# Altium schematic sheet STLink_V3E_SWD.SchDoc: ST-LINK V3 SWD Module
size A3; Date: Not used; ApprovedBy: Not used; CheckedBy: Not used; Author: Not used; CompanyName: STMicroelectronics; DrawnBy: Not used; Engineer: Not used; Organization: Not used; Address1: Not used; Address2: Not used; Address3: Not used; Address4: Not used; DocumentNumber: Not used; Revision: Not used; SheetNumber: 23; SheetTotal: 23
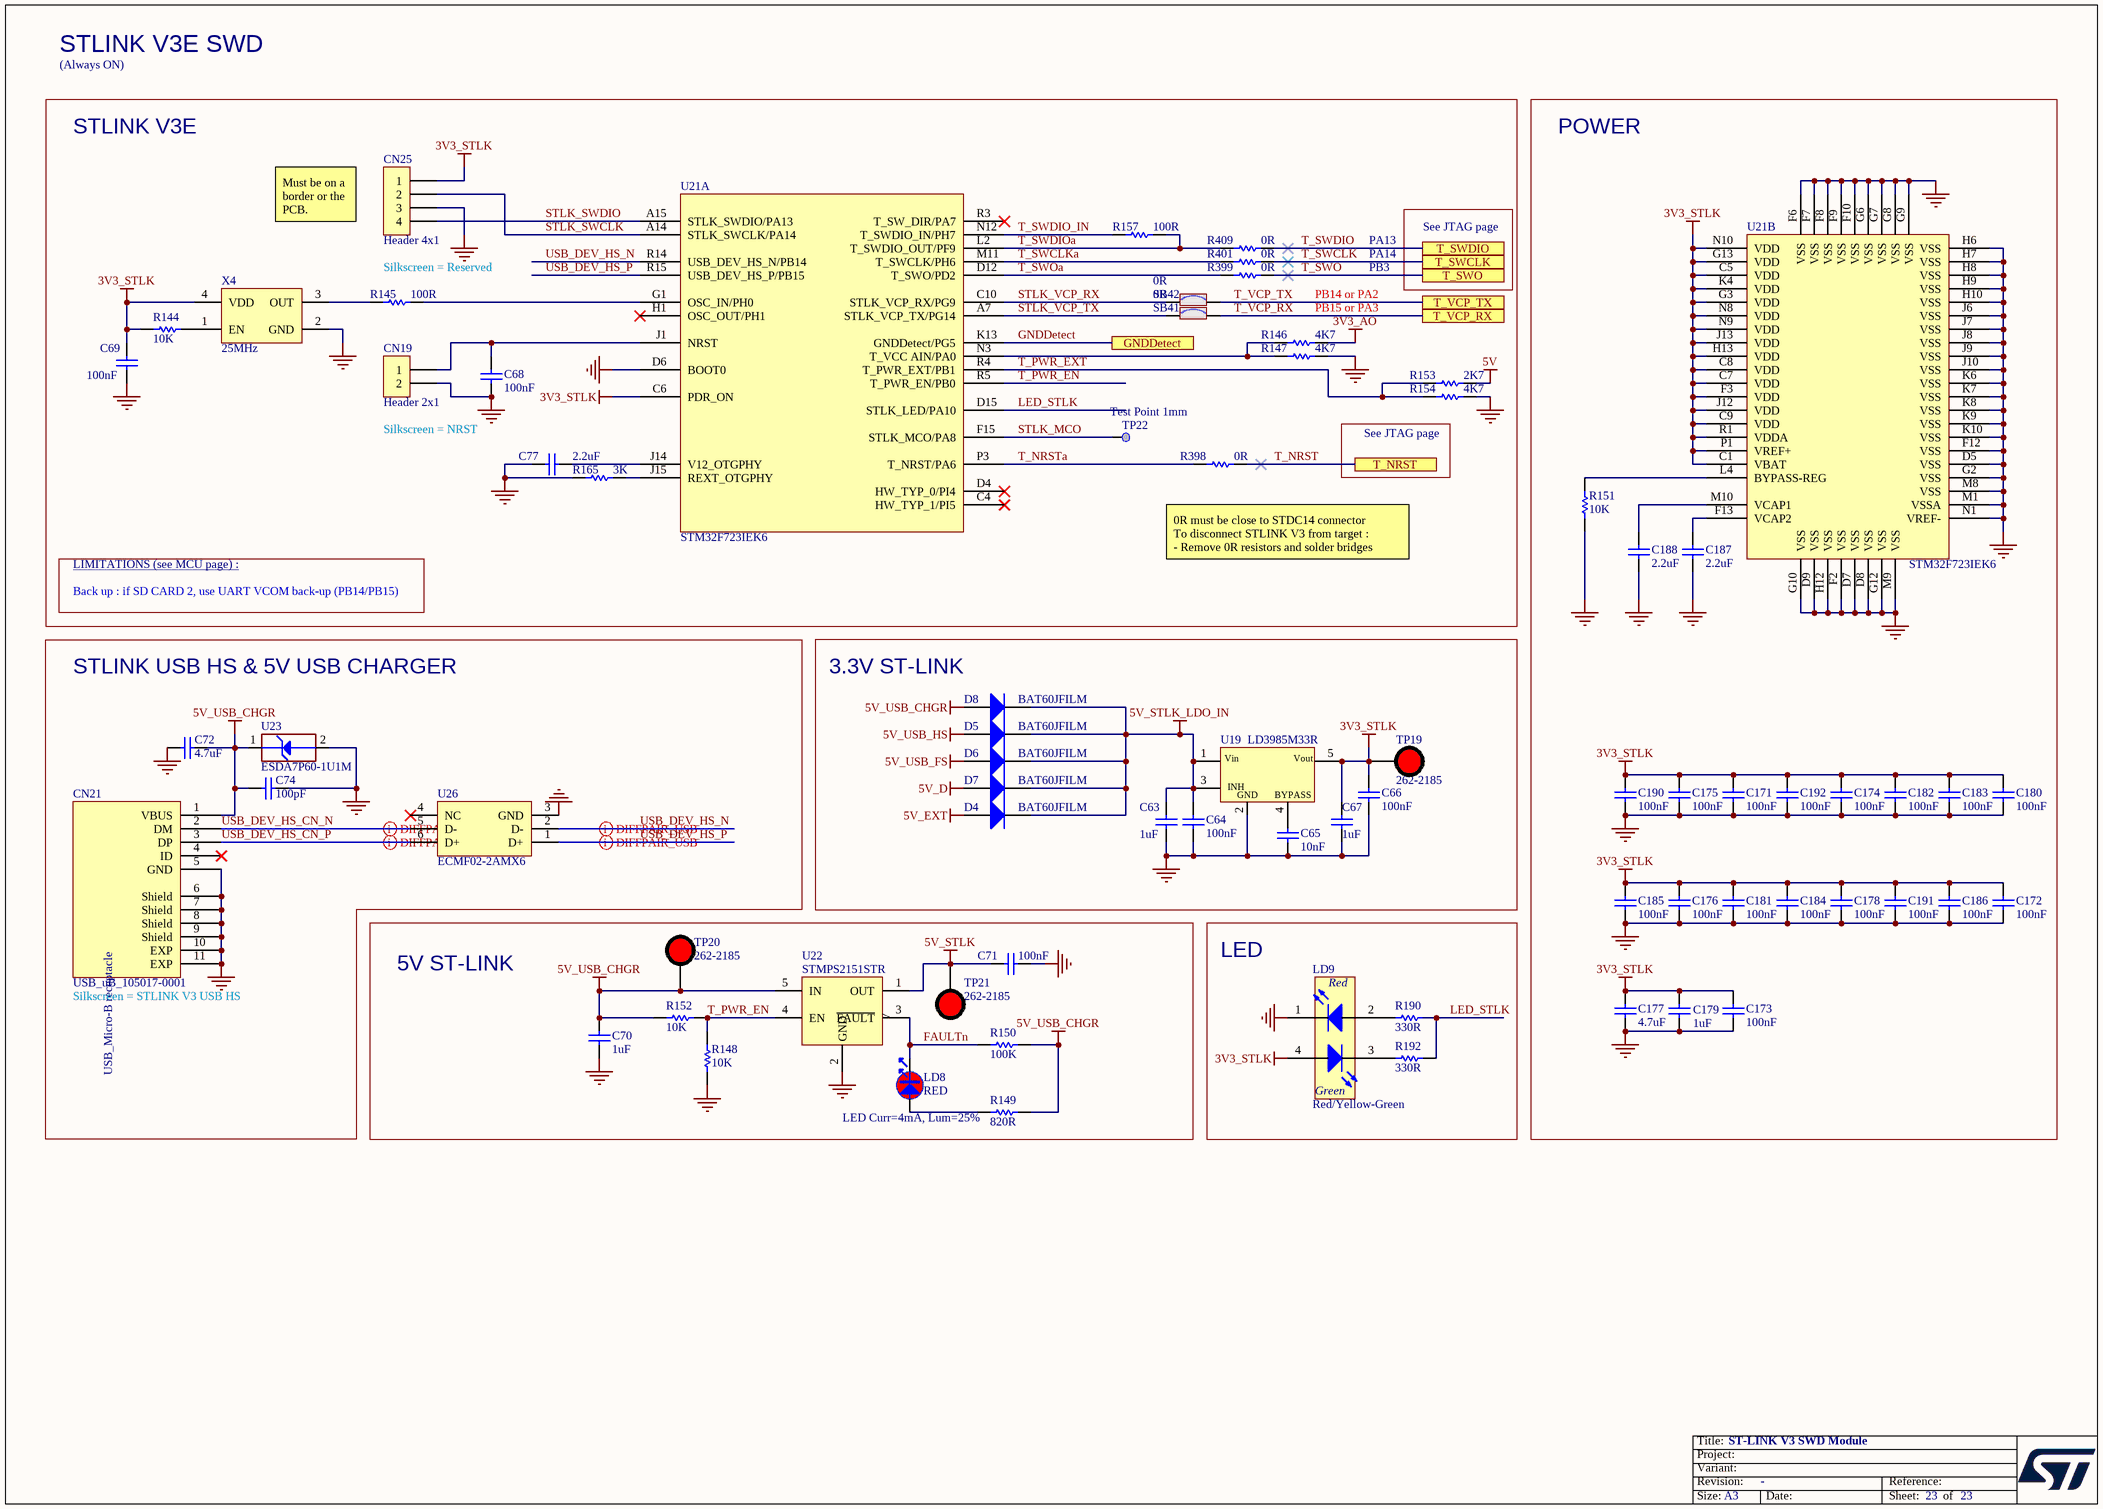
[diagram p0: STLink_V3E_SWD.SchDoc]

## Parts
C63  value 1uF  [C0603]  (hidden comment: Capacitor)
C64  value 100nF  [C0402]  (hidden comment: Capacitor)
C65  value 10nF  [C0402]  (hidden comment: Capacitor)
C66  value 100nF  [C0603]  (hidden comment: Capacitor)
C67  value 1uF  [C0603]  (hidden comment: Capacitor)
C68  value 100nF  [C0402]  (hidden comment: Capacitor)
C69  value 100nF  [C0402]  (hidden comment: Capacitor)
C70  value 1uF  [C0603]  (hidden comment: Capacitor)
C71  value 100nF  [C0402]  (hidden comment: Capacitor)
C72  value 4.7uF  [C0603]  (hidden comment: Capacitor)
C74  value 100pF  [C0402]  (hidden comment: Capacitor)
C77  value 2.2uF  [C0603]  (hidden comment: Capacitor)
C171  value 100nF  [C0402]  (hidden comment: Capacitor)
C172  value 100nF  [C0402]  (hidden comment: Capacitor)
C173  value 100nF  [C0402]  (hidden comment: Capacitor)
C174  value 100nF  [C0402]  (hidden comment: Capacitor)
C175  value 100nF  [C0402]  (hidden comment: Capacitor)
C176  value 100nF  [C0402]  (hidden comment: Capacitor)
C177  value 4.7uF  [C0603]  (hidden comment: Capacitor)
C178  value 100nF  [C0402]  (hidden comment: Capacitor)
C179  value 1uF  [C0603]  (hidden comment: Capacitor)
C180  value 100nF  [C0402]  (hidden comment: Capacitor)
C181  value 100nF  [C0402]  (hidden comment: Capacitor)
C182  value 100nF  [C0402]  (hidden comment: Capacitor)
C183  value 100nF  [C0402]  (hidden comment: Capacitor)
C184  value 100nF  [C0402]  (hidden comment: Capacitor)
C185  value 100nF  [C0402]  (hidden comment: Capacitor)
C186  value 100nF  [C0402]  (hidden comment: Capacitor)
C187  value 2.2uF  [C0603]  (hidden comment: Capacitor)
C188  value 2.2uF  [C0603]  (hidden comment: Capacitor)
C190  value 100nF  [C0402]  (hidden comment: Capacitor)
C191  value 100nF  [C0402]  (hidden comment: Capacitor)
C192  value 100nF  [C0402]  (hidden comment: Capacitor)
CN19  Header 2x1  [CON_SAMTEC_TSW-102-07-G-S]
CN21  value USB_uB_105017-0001  [CON_USBMICROB_MOLEX_105017-0001_H2P90]  (hidden comment: USB_uB_105017.0001)
CN25  Header 4x1  [CON_SAMTEC_TSW-104-07-G-S]
D4  BAT60JFILM  [DIO_SOD323]
D5  BAT60JFILM  [DIO_SOD323]
D6  BAT60JFILM  [DIO_SOD323]
D7  BAT60JFILM  [DIO_SOD323]
D8  BAT60JFILM  [DIO_SOD323]
LD8  value RED  [LED_0603_VISHAY_VLMS1300-GS08_RED_1A2K_H0P8]  (hidden comment: LED_red)
LD9  value Red/Yellow-Green  [LED_BI-GR_HSMF-A201-A00J1]  (hidden comment: LD_BICOLOR_CMS)
R144  value 10K  [R0402]  (hidden comment: Resistor)
R145  value 100R  [R0402]  (hidden comment: Resistor)
R146  value 4K7  [R0402]  (hidden comment: Resistor)
R147  value 4K7  [R0402]  (hidden comment: Resistor)
R148  value 10K  [R0402]  (hidden comment: Resistor)
R149  value 820R  [R0402]  (hidden comment: Resistor)
R150  value 100K  [R0402]  (hidden comment: Resistor)
R151  value 10K  [R0402]  (hidden comment: Resistor)
R152  value 10K  [R0402]  (hidden comment: Resistor)
R153  value 2K7  [R0402]  (hidden comment: Resistor)
R154  value 4K7  [R0402]  (hidden comment: Resistor)
R157  value 100R  [R0402]  (hidden comment: Resistor)
R165  value 3K  [R0402]  (hidden comment: Resistor)
R190  value 330R  [R0603]  (hidden comment: Resistor)
R192  value 330R  [R0603]  (hidden comment: Resistor)
R398  value 0R  [R0402]  (hidden comment: Resistor)
R399  value 0R  [R0402]  (hidden comment: Resistor)
R401  value 0R  [R0402]  (hidden comment: Resistor)
R409  value 0R  [R0402]  (hidden comment: Resistor)
SB41  value 0R  [SOLDER-BRIDGE_R0402-0R]  (hidden comment: SB_ON)
SB42  value 0R  [SOLDER-BRIDGE_R0402-0R]  (hidden comment: SB_ON)
TP19  value 262-2185  [TP_PTH-1MM_TEST-TERMINAL_RS_262-2185_RED]  (hidden comment: Test_pin_conn_red)
TP20  value 262-2185  [TP_PTH-1MM_TEST-TERMINAL_RS_262-2185_RED]  (hidden comment: Test_pin_conn_red)
TP21  value 262-2185  [TP_PTH-1MM_TEST-TERMINAL_RS_262-2185_RED]  (hidden comment: Test_pin_conn_red)
TP22  value Test Point 1mm  [TP_SMD_1MM]  (hidden comment: Test Point)  (no BOM)
U19  LD3985M33R  [REG_SOT23-5L]
U21  value STM32F723IEK6  [ICC_UFBGA201_176+25_10X10_P065]  (hidden comment: ST-LINKV3E_SWD)  (parts A,B of 2)
U22  STMPS2151STR  [MOS_SOT23-5L]
U23  value ESDA7P60-1U1M  [ESD_QFN2_1P6X1_P125]  (hidden comment: ESD-TRANSIL)
U26  ECMF02-2AMX6  [ESD_QFN-6L_1P7X1P5_P050]
X4  value 25MHz  [OSC_NDK_NZ2520SB_4P]  (hidden comment: OSCILLATOR_4_PINS)

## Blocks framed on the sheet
STLINK V3E: C68 C69 C77 CN19 CN25 R144-R147 R153 R154 R157 R165 R398 R399 R401 R409 SB41 SB42 TP22 U21 X4
POWER: C171-C188 C190-C192 R151 U21
STLINK USB HS & 5V USB CHARGER: C72 C74 CN21 U23 U26
3.3V ST-LINK: C63-C67 D4-D8 TP19 U19
5V ST-LINK: C70 C71 LD8 R148-R150 R152 TP20 TP21 U22
LED: LD9 R190 R192

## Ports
GNDDetect, T_NRST, T_SWCLK, T_SWDIO, T_SWO, T_VCP_RX, T_VCP_TX

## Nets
3V3_AO: R146.2
3V3_STLK: C66.2 C67.2 C69.2 C171.2 C172.2 C173.2 C174.2 C175.2 C176.2 C177.2 C178.2 C179.2 C180.2 C181.2 C182.2 C183.2 C184.2 C185.2 C186.2 C190.2 C191.2 C192.2 CN25.1 LD9.4(YellowGreen_anode) R144.1 TP19.1 U19.5(Vout) U21.C1(VBAT) U21.C5(VDD) U21.C6(PDR_ON) U21.C7(VDD) U21.C8(VDD) U21.C9(VDD) U21.F3(VDD) U21.G3(VDD) U21.G13(VDD) U21.H13(VDD) U21.J12(VDD) U21.J13(VDD) U21.K4(VDD) U21.N8(VDD) U21.N9(VDD) U21.N10(VDD) U21.P1(VREF+) U21.R1(VDDA) X4.4(VDD)
5V: R153.2
5V_D: D7.1(A)
5V_EXT: D4.1(A)
5V_STLK: C71.2 TP21.1 U22.1(OUT)
5V_STLK_LDO_IN: C63.1 C64.2 D4.2(K) D5.2(K) D6.2(K) D7.2(K) D8.2(K) U19.1(Vin) U19.3(CE)
5V_USB_CHGR: C70.2 C72.1 C74.1 CN21.1(VBUS) D8.1(A) R149.2 R150.2 R152.2 TP20.1 U22.5(IN) U23.1(IO1)
5V_USB_FS: D6.1(A)
5V_USB_HS: D5.1(A)
GND: C63.2 C64.1 C65.1 C66.1 C67.1 C68.1 C69.1 C70.1 C71.1 C72.2 C74.2 C77.1 C171.1 C172.1 C173.1 C174.1 C175.1 C176.1 C177.1 C178.1 C179.1 C180.1 C181.1 C182.1 C183.1 C184.1 C185.1 C186.1 C187.1 C188.1 C190.1 C191.1 C192.1 CN19.2 CN21.5(GND) CN21.6(Shield) CN21.7(Shield) CN21.8(Shield) CN21.9(Shield) CN21.10(EXP) CN21.11(EXP) CN25.3 LD9.1(RED_cathode) R147.2 R148.2 R151.1 R154.1 R165.1 U19.2(GND) U21.D5(VSS) U21.D6(BOOT0) U21.D7(VSS) U21.D8(VSS) U21.D9(VSS) U21.F2(VSS) U21.F6(VSS) U21.F7(VSS) U21.F8(VSS) U21.F9(VSS) U21.F10(VSS) U21.F12(VSS) U21.G2(VSS) U21.G6(VSS) U21.G7(VSS) U21.G8(VSS) U21.G9(VSS) U21.G10(VSS) U21.G12(VSS) U21.H6(VSS) U21.H7(VSS) U21.H8(VSS) U21.H9(VSS) U21.H10(VSS) U21.H12(VSS) U21.J6(VSS) U21.J7(VSS) U21.J8(VSS) U21.J9(VSS) U21.J10(VSS) U21.K6(VSS) U21.K7(VSS) U21.K8(VSS) U21.K9(VSS) U21.K10(VSS) U21.M1(VSSA) U21.M8(VSS) U21.M9(VSS) U21.N1(VREF-) U22.2(GND) U23.2(GND) U26.3(GND) X4.2(GND)
FAULTn: LD8.2 R150.1 U22.3(~{FAULT})
GNDDetect: U21.K13(GNDDetect/PG5) ; port GNDDetect
LED_STLK: R190.2 R192.2 U21.D15(STLK_LED/PA10)
STLK_MCO: TP22.1 U21.F15(STLK_MCO/PA8)
STLK_SWCLK: CN25.2 U21.A14(STLK_SWCLK/PA14)
STLK_SWDIO: CN25.4 U21.A15(STLK_SWDIO/PA13)
STLK_VCP_RX: SB42.1 U21.C10(STLK_VCP_RX/PG9)
STLK_VCP_TX: SB41.1 U21.A7(STLK_VCP_TX/PG14)
T_NRST: R398.2 ; port T_NRST
T_NRSTa: R398.1 U21.P3(T_NRST/PA6)
T_PWR_EN: R148.1 R152.1 U21.R5(T_PWR_EN/PB0) U22.4(EN)
T_PWR_EXT: R153.1 R154.2 U21.R4(T_PWR_EXT/PB1)
T_SWCLK: R401.2 ; port T_SWCLK
T_SWCLKa: R401.1 U21.M11(T_SWCLK/PH6)
T_SWDIO: R409.2 ; port T_SWDIO
T_SWDIO_IN: R157.1 U21.N12(T_SWDIO_IN/PH7)
T_SWDIOa: R157.2 R409.1 U21.L2(T_SWDIO_OUT/PF9)
T_SWO: R399.2 ; port T_SWO
T_SWOa: R399.1 U21.D12(T_SWO/PD2)
T_VCP_RX: SB41.2 ; port T_VCP_RX
T_VCP_TX: SB42.2 ; port T_VCP_TX
USB_DEV_HS_CN_N: CN21.2(DM) U26.5(D-)
USB_DEV_HS_CN_P: CN21.3(DP) U26.6(D+)
USB_DEV_HS_N: U21.R14(USB_DEV_HS_N/PB14) U26.2(D-)
USB_DEV_HS_P: U21.R15(USB_DEV_HS_P/PB15) U26.1(D+)
NetC65_2: C65.2 U19.4(BYPASS)
NetC68_2: C68.2 CN19.1 U21.J1(NRST)
NetC77_2: C77.2 U21.J14(V12_OTGPHY)
NetC187_2: C187.2 U21.F13(VCAP2)
NetC188_2: C188.2 U21.M10(VCAP1)
NetLD8_1: LD8.1 R149.1
NetLD9_2: LD9.2(Red_anode) R190.1
NetLD9_3: LD9.3(YellowGreen_cathode) R192.1
NetR144_2: R144.2 X4.1(EN)
NetR145_1: R145.1 X4.3(OUT)
NetR145_2: R145.2 U21.G1(OSC_IN/PH0)
NetR146_1: R146.1 R147.1 U21.N3(T_VCC_AIN/PA0)
NetR151_2: R151.2 U21.L4(BYPASS-REG)
NetR165_2: R165.2 U21.J15(REXT_OTGPHY)

Not connected (* = marked no-connect by the designer): CN21 4(ID)*; U21 C4(HW_TYP_1/PI5)* D4(HW_TYP_0/PI4)* H1(OSC_OUT/PH1)* R3(T_SW_DIR/PA7)*; U26 4(NC)*

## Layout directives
differential pair; rule Impedance Constraint [Min = 85.00    Max = 95.00    ]: USB_DEV_HS_CN_N, USB_DEV_HS_CN_P, USB_DEV_HS_N, USB_DEV_HS_P

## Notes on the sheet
- STLINK V3E SWD
- (Always ON)
- Must be on a border or the PCB.
- PA13
- See JTAG page
- Silkscreen = Reserved
- PB14 or PA2
- PB15 or PA3
- PA14
- PB3
- Silkscreen = NRST
- LIMITATIONS (see MCU page) :
- (near R398) 0R must be close to STDC14 connector
  To disconnect STLINK V3 from target :
  - Remove 0R resistors and solder bridges
- Back up : if SD CARD 2, use UART VCOM back-up (PB14/PB15)
- (near CN21) Silkscreen = STLINK V3 USB HS
- LED Curr=4mA, Lum=25%

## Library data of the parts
C63 = MCD-00238: Capacitor, MLCC, 1uF, 6V3, X5R, 10%, 0603, T=0,8mm; Manufacturer_Part_Number: CC0603KRX5R5BB105; Manufacturer: YAGEO; Part_Preference: Recommended; Provided_By: SUBCO; ECCN_US: EAR99; ECCN_EU: NEC; Component_Country_Of_Origin: China; ID: 2629; ShowFields: YES
C64 C68 C69 C71 C171-C176 C178 C180-C186 C190-C192 = MCD-00006: Capacitor, MLCC, 100nF, 16V, X7R, 10%, 0402, T=0.5mm; Manufacturer_Part_Number: CC0402KRX7R7BB104; Manufacturer: YAGEO; Alternate_Manufacturer_Part_Number: GCM155R71C104KA55D; Alternate_Manufacturer: MURATA; Part_Preference: Recommended; Partial_Alternate_Internal_Part_Number: MCD-03299; Provided_By: SUBCO; ECCN_US: EAR99; ECCN_EU: NEC; Component_Country_Of_Origin: China; ID: 2474; Order_Code_RS: 9402047; ShowFields: YES
C65 = MCD-00011: Capacitor, MLCC, 10nF, 16V, X7R, 10%, 0402, T=0.5mm; Manufacturer_Part_Number: CC0402KRX7R7BB103; Manufacturer: YAGEO; Part_Preference: Recommended; Provided_By: SUBCO; ECCN_US: EAR99; ECCN_EU: NEC; Component_Country_Of_Origin: China; ID: 2469; Order_Code_RS: 3019275; ShowFields: YES
C66 = MCD-00211: Capacitor, MLCC, 100nF, 16V, X7R, 10%, 0603, T=0,8mm; Manufacturer_Part_Number: CC0603KRX7R7BB104; Manufacturer: YAGEO; Part_Preference: Recommended; Partial_Alternate_Internal_Part_Number: MCD-01099; Provided_By: SUBCO; ECCN_US: EAR99; ECCN_EU: NEC; Component_Country_Of_Origin: China; ID: 2659; Order_Code_RS: 669-8763; ShowFields: YES
C67 C70 C179 = MCD-00010: Capacitor, MLCC, 1uF, 16V, X5R, 10%, 0603, T=0,8mm; Manufacturer_Part_Number: CC0603KRX5R7BB105; Manufacturer: YAGEO; Part_Preference: Recommended; Provided_By: SUBCO; ECCN_US: EAR99; ECCN_EU: NEC; Component_Country_Of_Origin: China; ID: 2470; Order_Code_RS: 2370680; ShowFields: YES
C72 C177 = MCD-00009: Capacitor, MLCC, 4.7uF, 16V, X5R, 10%, 0603, T=0.8mm; Manufacturer_Part_Number: CC0603KRX5R7BB475; Manufacturer: YAGEO; Part_Preference: Recommended; Partial_Alternate_Internal_Part_Number: MCD-03565; Provided_By: SUBCO; ECCN_US: EAR99; ECCN_EU: NEC; Alternate_EMS: A; Component_Country_Of_Origin: China; ID: 2471; ShowFields: YES
C74 = MCD-00205: Capacitor, MLCC, 100pF, 50V, NPO, 5%, 0402, T=0,5mm; Manufacturer_Part_Number: CC0402JRNPO9BN101; Manufacturer: YAGEO; Part_Preference: Recommended; Provided_By: SUBCO; ECCN_US: EAR99; ECCN_EU: NEC; Component_Country_Of_Origin: China; ID: 2658; ShowFields: YES
C77 C187 C188 = MCD-00012: Capacitor, MLCC, 2.2uF, 10V, X5R, 10%, 0603, T=0,8mm; Manufacturer_Part_Number: CC0603KRX5R6BB225; Manufacturer: YAGEO; Alternate_Manufacturer_Part_Number: C0603C225K8PACTU; Alternate_Manufacturer: KEMET; BMS_Part_Number: 9142010; Part_Preference: Recommended; Partial_Alternate_Internal_Part_Number: MCD-00551; Provided_By: SUBCO; ECCN_US: EAR99; ECCN_EU: NEC; Component_Country_Of_Origin: China; ID: 2467; Order_Code_RS: 2370679; ShowFields: YES
CN19 = MCD-00032: Header, 2x1, 2,54mm, VR, TH, Height 5.84mm/2.54mm; Part_Type: Connector; Manufacturer_Part_Number: TSW-102-07-G-S; Manufacturer: SAMTEC; Alternate_Manufacturer_Part_Number: 313102S111116; Alternate_Manufacturer: JIUBABA; Part_Preference: Recommended; Provided_By: SUBCO; Component_Country_Of_Origin: China, Costa Rica, Malaysia, USA, Vietnam; ID: 2484; Order_Code_RS: 2505044; ShowFields: YES
CN21 = MCD-00028: USB-MICRO-B, 0.65mm, RA, SMT, Bottom Mount,; Manufacturer_Part_Number: 1050170001; Manufacturer: MOLEX; Part_Type: Connector; Part_Preference: Recommended; Provided_By: SUBCO; Component_Country_Of_Origin: Unknown; ID: 2489; Order_Code_RS: 2293836; ShowFields: YES
CN25 = MCD-00029: Header, 4x1, 2,54mm, VR, TH, Height 5.84mm/2.54mm; Manufacturer_Part_Number: TSW-104-07-G-S; Manufacturer: SAMTEC; Part_Type: Connector; Part_Preference: Recommended; Provided_By: SUBCO; Component_Country_Of_Origin: China, Costa Rica, Malaysia, USA, Vietnam; ID: 2487; Order_Code_RS: 2667450; ShowFields: YES
D4-D8 = MCD-00034: Manufacturer: STMICROELECTRONICS; Part_Type: Diode; BMS_Part_Number: 9151097; Manufacturer_HQ_COO: EU; Part_Preference: Recommended; Provided_By: SUBCO with ST control; ECCN_US: EAR99; ECCN_EU: NEC; Component_Country_Of_Origin: China; ID: 2483; Order_Code_RS: 714-6879; ShowFields: YES
LD8 = MCD-00587: LED Red, 0603 SMD, 2V Forward Voltage; Part_Type: Display; Manufacturer_Part_Number: VLMS1300-GS08; Manufacturer: VISHAY; Alternate_Manufacturer_Part_Number: LS Q976-NR-1; Alternate_Manufacturer: OSRAM OPTO SEMICONDUCTORS; Full_Alternate_Internal_Part_Number: MCD-02401; Part_Preference: Recommended; Provided_By: SUBCO; Component_Country_Of_Origin: China; ID: 3154; ShowFields: YES
LD9 = MCD-02402: LED Bicolor, Red/Yellow-Green , 2V, 20mA, 4-PLCC; Part_Type: Display; Manufacturer_Part_Number: 67-22SURSYGC/S530-A2/TR8; Manufacturer: EVERLIGHT; Part_Preference: Not recommended; Full_Alternate_Internal_Part_Number: MCD-00051, MCD-02631; ShowFields: YES; ID: 4508
R144 R148 R151 R152 = MCD-00053: Resistor,10K,0402,1%,1/16W; Manufacturer_Part_Number: RC0402FR-0710KL; Manufacturer: YAGEO; BMS_Part_Number: 9131590; Part_Preference: Recommended; Provided_By: SUBCO; ECCN_US: EAR99; ECCN_EU: NEC; Component_Country_Of_Origin: China; ID: 2539; Order_Code_RS: 9239359; ShowFields: YES
R145 R157 = MCD-00067: Resistor,100R,0402,1%,1/16W; Manufacturer_Part_Number: RC0402FR-07100RL; Manufacturer: YAGEO; Part_Preference: Recommended; Provided_By: SUBCO; ECCN_US: EAR99; ECCN_EU: NEC; Component_Country_Of_Origin: China; ID: 2527; Order_Code_RS: 9239111; ShowFields: YES
R146 R147 R154 = MCD-00065: Resistor,4K7,0402,1%,1/16W; Manufacturer_Part_Number: RC0402FR-074K7L; Manufacturer: YAGEO; Alternate_Manufacturer_Part_Number: RT0402FRE074K7L; Part_Preference: Recommended; Partial_Alternate_Internal_Part_Number: MCD-03300; Provided_By: SUBCO; ECCN_US: EAR99; ECCN_EU: NEC; Component_Country_Of_Origin: China; ID: 2526; Order_Code_RS: 9239316; ShowFields: YES
R149 = MCD-00527: Resistor,820R,0402,1%,1/16W; Manufacturer_Part_Number: RC0402FR-07820RL; Manufacturer: YAGEO; Part_Preference: Recommended; Provided_By: SUBCO; ECCN_US: EAR99; ECCN_EU: NEC; Component_Country_Of_Origin: China; ID: 3217; ShowFields: YES
R150 = MCD-00059: Resistor,100K,0402,1%,1/16W; Manufacturer_Part_Number: RC0402FR-07100KL; Manufacturer: YAGEO; Alternate_Manufacturer_Part_Number: RT0402FRE07100KL; Part_Preference: Recommended; Partial_Alternate_Internal_Part_Number: MCD-03301; Provided_By: SUBCO; ECCN_US: EAR99; ECCN_EU: NEC; Component_Country_Of_Origin: China; ID: 2533; Order_Code_RS: 2421891; ShowFields: YES
R153 = MCD-00055: Resistor,2K7,0402,1%,1/16W; Manufacturer_Part_Number: RC0402FR-072K7L; Manufacturer: YAGEO; Part_Preference: Recommended; Provided_By: SUBCO; ECCN_US: EAR99; ECCN_EU: NEC; Component_Country_Of_Origin: China; ID: 2535; Order_Code_RS: 9239286; ShowFields: YES
R165 = MCD-00185: Resistor,3K,0402,1%,1/16W; Manufacturer_Part_Number: RC0402FR-073KL; Manufacturer: YAGEO; Part_Preference: Recommended; Provided_By: SUBCO; ECCN_US: EAR99; ECCN_EU: NEC; Component_Country_Of_Origin: China; ID: 2682; ShowFields: YES
R190 R192 = MCD-00197: Resistor,330R,0603,1%,1/10W; Manufacturer_Part_Number: RC0603FR-07330RL; Manufacturer: YAGEO; BMS_Part_Number: 9129729; Part_Preference: Recommended; Provided_By: SUBCO; ECCN_US: EAR99; ECCN_EU: NEC; Component_Country_Of_Origin: China; ID: 2672; ShowFields: YES
R398 R399 R401 R409 = MCD-00052: Resistor,0R,0402,5%,1/16W; Manufacturer_Part_Number: RC0402JR-070RL; Manufacturer: YAGEO; Part_Preference: Recommended; Provided_By: SUBCO; ECCN_US: EAR99; ECCN_EU: NEC; Component_Country_Of_Origin: China; ID: 2540; Order_Code_RS: 9232516RL; ShowFields: YES
SB41 SB42 = MCD-01618: Solder Bridge 0402 ON; Part_Type: Resistor; Manufacturer_Part_Number: RC0402JR-070RL; Manufacturer: YAGEO; Part_Preference: Recommended; Provided_By: SUBCO; Component_Country_Of_Origin: China; ID: 3718; Order_Code_RS: 618-5804; ShowFields: YES
TP19-TP21 = MCD-00712: RS Pro 1mm Red Test Terminal; Part_Type: Misc; Manufacturer: RS PRO; Part_Preference: Recommended; Provided_By: SUBCO; Component_Country_Of_Origin: UK; ID: 3035; ShowFields: YES
TP22 = MCD-00074: Test Point 1mm; Part_Type: Misc; Part_Preference: Recommended; Component_Country_Of_Origin: Unknown; ID: 2518; ShowFields: YES
U19 = MCD-00086: Ultra low drop-low noise BiCMOS voltage, regulators low ESR capacitors compatible; Manufacturer: STMICROELECTRONICS; Part_Type: IC; BMS_Part_Number: 9176161; Manufacturer_HQ_COO: EU; Part_Preference: Recommended; Provided_By: SUBCO with ST control; ECCN_US: EAR99; ECCN_EU: NEC; Component_Country_Of_Origin: China; ID: 2506; Order_Code_RS: 168-6500; ShowFields: YES
U21 = MCD-00596: STM32F723IEK  (STM32F7) BGA176; Part_Type: IC; Manufacturer: STMICROELECTRONICS; BMS_Part_Number: 9175300; Manufacturer_HQ_COO: EU; Part_Preference: Recommended; Provided_By: SUBCO with ST control; ECCN_US: 3A991A2; ECCN_EU: NEC; Component_Country_Of_Origin: Philippines; ID: 3144; Order_Code_RS: 135-8268; ShowFields: YES
U22 = MCD-00159: 500mA, Enhanced single channel power switches with active high enable pin; Part_Type: IC; Manufacturer: STMICROELECTRONICS; Alternate_Manufacturer_Part_Number: TPS2051C; Alternate_Manufacturer: TEXAS INSTRUMENTS; BMS_Part_Number: 9159009; Part_Preference: Recommended; Provided_By: SUBCO with ST control; ECCN_US: EAR99; ECCN_EU: NEC; Component_Country_Of_Origin: Malaysia; ID: 2708; Order_Code_RS: 165-5516; ShowFields: YES
U23 = MCD-00251: High power transient voltage suppressor, 7V breakdown; Part_Type: Diode; Manufacturer: STMICROELECTRONICS; BMS_Part_Number: 9179042; Manufacturer_HQ_COO: EU; Part_Preference: Recommended; Provided_By: SUBCO with ST control; ECCN_US: EAR99; ECCN_EU: NEC; Component_Country_Of_Origin: China; ID: 2618; Order_Code_RS: 110-6381; ShowFields: YES
U26 = MCD-00649: Common mode filter with ESD protection for USB 2.0 interface; Part_Type: Diode; Manufacturer: STMICROELECTRONICS; BMS_Part_Number: 9151138; Manufacturer_HQ_COO: EU; Part_Preference: Recommended; Provided_By: SUBCO with ST control; ECCN_US: EAR99; ECCN_EU: NEC; Component_Country_Of_Origin: China; ID: 3094; Order_Code_RS: 880-5276; ShowFields: YES
X4 = MCD-00597: Oscillator 25Mhz, +-50ppm, Vcc:3.3V typ, square wave: [0.1Vcc;0.9Vcc], Enable pin, SMD; Part_Type: Crystal_Osc; Manufacturer_Part_Number: NZ2520SH-25MHZ-END4869C; Manufacturer: NDK; Alternate_Manufacturer_Part_Number: NZ2520SB 25MHz END4869B; BMS_Part_Number: 9157050; Part_Preference: Recommended; Provided_By: SUBCO; ECCN_US: EAR99; ECCN_EU: NEC; Component_Country_Of_Origin: Unknown; ID: 3148; ShowFields: YES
